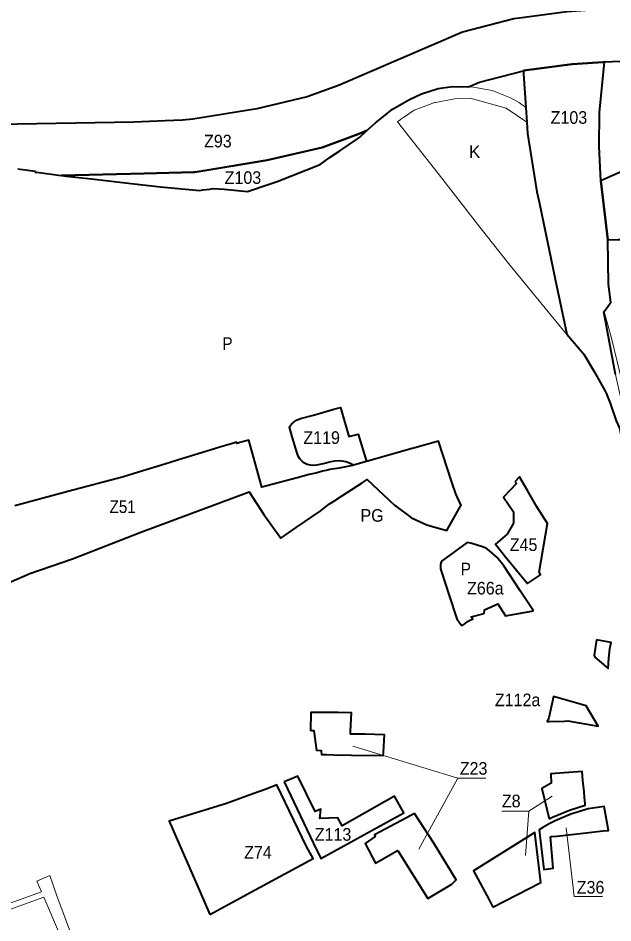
# Model space of a CAD drawing. Extents: x -650276 to -642489, y -1074311 to -1066658.
# Drawn here: x -649001 to -647871, y -1070690 to -1068970 of the extents above; entities that cross this region are included whole.
import ezdxf

# ---------------------------------------------------------------- set-up
doc = ezdxf.new("R2010")
doc.units = 0
doc.header["$LTSCALE"] = 9.6
for name, color, linetype, lineweight in [('44', 7, 'Continuous', 40), ('45', 7, 'Continuous', 40), ('46', 7, 'Continuous', 13), ('47', 7, 'Continuous', 13), ('48', 7, 'Continuous', 13), ('60', 7, 'Continuous', 35)]:
    doc.layers.add(name, color=color, linetype=linetype, lineweight=lineweight)

msp = doc.modelspace()

# ---------------------------------------------------------------- linework, layer by layer
at = {"layer": '44'}
for points in [[(-647749.978, -1068953.416), (-647850.043, -1068951.099), (-647864.531, -1068951.823), (-647895.901, -1068953.392), (-647958.168, -1068957.73), (-648038.596, -1068968.281), (-648038.596, -1068968.281), (-648038.746, -1068968.301), (-648058.764, -1068970.927)], [(-648058.764, -1068970.927), (-648156.739, -1068996.273), (-648392.002, -1069097.554), (-648451.865, -1069119.456), (-648547.243, -1069141.81), (-648668.959, -1069161.838), (-648688.912, -1069163.603), (-648721.315, -1069164.952), (-648781.015, -1069167.44), (-649076.02, -1069172.683)], [(-648040.456, -1069069.483), (-648039.666, -1069069.279), (-647948.18, -1069057.276)], [(-647948.18, -1069057.276), (-648039.666, -1069069.279), (-648040.456, -1069069.483)], [(-647948.18, -1069057.276), (-647889.927, -1069053.218), (-647886.615, -1069053.052)], [(-647886.615, -1069053.052), (-647889.927, -1069053.218), (-647948.18, -1069057.276)], [(-647887.087, -1069527.229), (-647878.73, -1069515.45), (-647874.75, -1069509.84), (-647878.93, -1069475.09), (-647880.326, -1069390.832), (-647893.553, -1069279.021), (-647896.67, -1069213.573), (-647896.362, -1069149.171), (-647886.615, -1069053.052)], [(-647886.615, -1069053.052), (-647856.541, -1069051.548), (-647756.441, -1069053.207), (-647708.401, -1069056.275), (-647511.94, -1069076.703), (-647426.417, -1069084.624), (-647344.902, -1069091.02), (-647270.522, -1069094.255), (-647197.498, -1069094.255), (-647123.648, -1069091.043), (-647065.688, -1069087.73)], [(-648665.007, -1069262.694), (-648527.693, -1069239.938), (-648423.173, -1069215.44), (-648354.978, -1069190.492), (-648338.523, -1069183.389), (-648322.14, -1069168.56), (-648306.83, -1069156.57), (-648289.25, -1069142.79), (-648257.5, -1069124.41), (-648234.22, -1069113.6), (-648202.46, -1069103.3), (-648175.65, -1069099.64), (-648144.866, -1069099.987), (-648124.327, -1069091.181), (-648040.705, -1069069.547), (-648040.456, -1069069.483)], [(-648040.456, -1069069.483), (-648040.537, -1069075.531), (-648036.291, -1069139.458), (-648034.421, -1069167.61)], [(-648526.15, -1069286.21), (-648508.95, -1069280.01), (-648427.08, -1069247.75), (-648407.73, -1069233.88), (-648389.91, -1069221.86), (-648355.81, -1069198.88), (-648351.77, -1069195.88), (-648338.523, -1069183.389), (-648354.978, -1069190.492)], [(-648034.421, -1069167.61), (-648033, -1069189), (-648015, -1069300), (-648010.092, -1069322.087), (-647980.331, -1069465.915), (-647958.34, -1069570.699), (-647925.99, -1069608.57)], [(-648354.978, -1069190.492), (-648423.173, -1069215.44), (-648527.693, -1069239.938), (-648652.716, -1069260.657)], [(-649001.3, -1069255.92), (-648968.49, -1069260.36), (-648968.05, -1069263.06), (-648965.8, -1069262.75), (-648937.91, -1069266.51), (-648924.13, -1069268.21), (-648918.889, -1069268.875)], [(-648918.889, -1069268.875), (-648761.189, -1069265.035), (-648666.827, -1069262.738), (-648665.007, -1069262.694)], [(-648666.827, -1069262.738), (-648761.189, -1069265.035), (-648918.889, -1069268.875), (-648909.86, -1069270.02), (-648861.49, -1069275.34), (-648785.92, -1069284.2), (-648730.66, -1069290.43), (-648730.66, -1069290.43), (-648655.53, -1069297.18), (-648650.06, -1069296.39), (-648636.85, -1069294.49)], [(-648652.716, -1069260.657), (-648665.007, -1069262.694), (-648666.827, -1069262.738)], [(-648636.85, -1069294.49), (-648630.82, -1069293.63), (-648609.425, -1069295.033), (-648603.228, -1069295.53), (-648565.18, -1069299.46), (-648526.15, -1069286.21)], [(-647865.69, -1069647.32), (-647887.649, -1069528.021), (-647887.087, -1069527.229)], [(-647925.99, -1069608.57), (-647906.16, -1069641.48), (-647885.665, -1069678.788), (-647885.663, -1069678.794), (-647883.51, -1069682.71), (-647875.82, -1069701.85)], [(-647875.82, -1069701.85), (-647864.19, -1069735.12), (-647858.44, -1069749.43), (-647852.63, -1069775.7), (-647850.66, -1069785.74), (-647849.165, -1069793.367), (-647843.74, -1069817.63), (-647841.402, -1069792.351)]]:
    msp.add_lwpolyline(points, dxfattribs=at)
msp.add_lwpolyline([(-647860.52, -1069390.72), (-647848.24, -1069390.65), (-647845.25, -1069390.07), (-647843.41, -1069389.23), (-647841.81, -1069387.99), (-647840.42, -1069386.51), (-647839.4, -1069384.73), (-647838.79, -1069382.86), (-647836.2, -1069362.68), (-647832.29, -1069338.58), (-647832.29, -1069338.58), (-647831.19, -1069320.69), (-647830.23, -1069305.38), (-647826.928, -1069253.199), (-647848.17, -1069259.21), (-647858.37, -1069263.03), (-647893.553, -1069279.017), (-647880.326, -1069390.832)], close=True, dxfattribs=at)
msp.add_arc((-648354.978, -1069190.492), 0.000000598, 264.13978, 298.69712, dxfattribs=at)
at = {"layer": '45'}
for points in [[(-648338.933, -1069812.492), (-648363.563, -1069819.352), (-648371.093, -1069815.602), (-648377.983, -1069813.332), (-648385.093, -1069811.952), (-648392.333, -1069811.482), (-648399.563, -1069811.922), (-648406.723, -1069813.272), (-648414.54, -1069815.288), (-648415.873, -1069815.632), (-648430.764, -1069818.704), (-648433.853, -1069819.342), (-648439.773, -1069820.012), (-648445.683, -1069819.552), (-648451.413, -1069818.022), (-648456.763, -1069815.432), (-648461.523, -1069811.902), (-648465.553, -1069807.532), (-648468.703, -1069802.482), (-648470.853, -1069796.942), (-648480.15, -1069765.358), (-648485.323, -1069747.432), (-648485.023, -1069746.592), (-648483.157, -1069743.818), (-648481.673, -1069741.612), (-648477.273, -1069737.482), (-648475.905, -1069736.566), (-648472.283, -1069734.142), (-648464.333, -1069730.932), (-648439.683, -1069724.232), (-648401.171, -1069713.196), (-648388.514, -1069709.779), (-648372.522, -1069765.283), (-648354.898, -1069760.328)], [(-648057.11, -1069851.12), (-648053.61, -1069854.64), (-648078.54, -1069880.01), (-648059.32, -1069908.27), (-648059.5, -1069929.52), (-648071.58, -1069950.39), (-648093.67, -1069969.42), (-648074.96, -1069993.46), (-648032.85, -1070044.73), (-648008.18, -1070028.25), (-648010.44, -1070023.66), (-648010.94, -1070022.65), (-647994.71, -1069930.53), (-648015.11, -1069898.98), (-648032.94, -1069867.46), (-648048.08, -1069841.95)], [(-648057.11, -1069851.12), (-648053.61, -1069854.64), (-648078.54, -1069880.01), (-648059.32, -1069908.27), (-648059.5, -1069929.52), (-648071.58, -1069950.39), (-648093.67, -1069969.42), (-648074.96, -1069993.46), (-648032.85, -1070044.73), (-648008.18, -1070028.25), (-648010.44, -1070023.66), (-648010.94, -1070022.65), (-647994.71, -1069930.53), (-648015.11, -1069898.98), (-648032.94, -1069867.46), (-648048.08, -1069841.95)], [(-647902.17, -1070151.64), (-647906.6, -1070180.65), (-647905.17, -1070184.5), (-647879.81, -1070206.08), (-647878.18, -1070186.33), (-647876.74, -1070168.88), (-647873.97, -1070156.58)], [(-647902.17, -1070151.64), (-647906.6, -1070180.65), (-647905.17, -1070184.5), (-647879.81, -1070206.08), (-647878.18, -1070186.33), (-647876.74, -1070168.88), (-647873.97, -1070156.58)], [(-647962.82, -1070305.9), (-647956.36, -1070305.77), (-647898.82, -1070315.51), (-647921.51, -1070276.76), (-647979.24, -1070260.71), (-647983.6, -1070259.5), (-647992.71, -1070300.01), (-647995.46, -1070306.55), (-647991.12, -1070306.46)], [(-648444.85, -1070324.47), (-648444.15, -1070289.16), (-648428.98, -1070288.92), (-648416.93, -1070288.85), (-648392.94, -1070289.25), (-648368.25, -1070289.71), (-648370.07, -1070325.94), (-648370.07, -1070329.902), (-648341.46, -1070330.48), (-648305.47, -1070331.23), (-648307.13, -1070365.57), (-648307.67, -1070371.78), (-648367.67, -1070371.16), (-648401.35, -1070370.5), (-648414.75, -1070370.24), (-648424.05, -1070370), (-648424.31, -1070362.21), (-648433.46, -1070361.94), (-648437.65, -1070328.8), (-648438.296, -1070324.598)], [(-648444.85, -1070324.47), (-648444.15, -1070289.16), (-648428.98, -1070288.92), (-648416.93, -1070288.85), (-648392.94, -1070289.25), (-648368.25, -1070289.71), (-648370.07, -1070325.94), (-648370.07, -1070329.902), (-648341.46, -1070330.48), (-648305.47, -1070331.23), (-648307.13, -1070365.57), (-648307.67, -1070371.78), (-648367.67, -1070371.16), (-648401.35, -1070370.5), (-648414.75, -1070370.24), (-648424.05, -1070370), (-648424.31, -1070362.21), (-648433.46, -1070361.94), (-648437.65, -1070328.8), (-648438.296, -1070324.598)], [(-647991.539, -1070492.016), (-647985.19, -1070488.804), (-647953.251, -1070475.276), (-647923.247, -1070465.749), (-647923.53, -1070462.75), (-647924.63, -1070451.09), (-647925.5, -1070439.63), (-647926.53, -1070429.76), (-647927.67, -1070418.74), (-647929.24, -1070401.97), (-647988.86, -1070405.95), (-647988.11, -1070423.93), (-648005.668, -1070434.145)], [(-648495.666, -1070421.476), (-648439.409, -1070538.729), (-648425.835, -1070567.021), (-648267.801, -1070480.55), (-648285.75, -1070448.49), (-648385.085, -1070505.351), (-648393.14, -1070490.07), (-648427.41, -1070491.08), (-648426.05, -1070473.34), (-648436.22, -1070478.01), (-648469.77, -1070410.47), (-648481.18, -1070415.62)], [(-648495.666, -1070421.476), (-648439.409, -1070538.729), (-648425.835, -1070567.021), (-648267.801, -1070480.55), (-648285.75, -1070448.49), (-648385.085, -1070505.351), (-648393.14, -1070490.07), (-648427.41, -1070491.08), (-648426.05, -1070473.34), (-648436.22, -1070478.01), (-648469.77, -1070410.47), (-648481.18, -1070415.62)], [(-648636.757, -1070673.431), (-648550.72, -1070626.869), (-648440.531, -1070567.236), (-648452.97, -1070544.21), (-648509.227, -1070426.957), (-648526.28, -1070433.85), (-648538.611, -1070438.388), (-648546.377, -1070441.246), (-648604.92, -1070462.79), (-648714.161, -1070496.376), (-648655.178, -1070631.294)], [(-647950.48, -1070482.79), (-647980.4, -1070495.463), (-647990.295, -1070500.352), (-648003.85, -1070508.218), (-648010.831, -1070512.588), (-648002, -1070588), (-647984.03, -1070585.46), (-647989.5, -1070525.73), (-647987.436, -1070525.508), (-647977.41, -1070524.43), (-647927.14, -1070519), (-647889.27, -1070514.92), (-647879.89, -1070513.91), (-647879.16, -1070513.83), (-647887.08, -1070468.54), (-647899.87, -1070470.04), (-647917.98, -1070472.47)], [(-648247.67, -1070481.57), (-648262.69, -1070489.67), (-648323.59, -1070522.48), (-648322.18, -1070525.44), (-648341.41, -1070538.42), (-648322.16, -1070575.76), (-648289.22, -1070557.15), (-648279.736, -1070551.783), (-648278.89, -1070553.14), (-648222.58, -1070643.48), (-648176.54, -1070616.09), (-648168.575, -1070607.847), (-648211, -1070538)], [(-648247.67, -1070481.57), (-648262.69, -1070489.67), (-648323.59, -1070522.48), (-648322.18, -1070525.44), (-648341.41, -1070538.42), (-648322.16, -1070575.76), (-648289.22, -1070557.15), (-648279.736, -1070551.783), (-648278.89, -1070553.14), (-648222.58, -1070643.48), (-648176.54, -1070616.09), (-648168.575, -1070607.847), (-648211, -1070538)], [(-648098.637, -1070659.682), (-648007.838, -1070612.851), (-648019, -1070518), (-648135.47, -1070590.61), (-648105.98, -1070645.91)]]:
    msp.add_lwpolyline(points, close=True, dxfattribs=at)
for points in [[(-649048.918, -1070055.852), (-648978.654, -1070025.669), (-648897.735, -1069997.25), (-648767.83, -1069946.87), (-648562.242, -1069870.301), (-648533.79, -1069913.49), (-648502.048, -1069957.969), (-648472.6, -1069937.81), (-648426.82, -1069906.88), (-648409.44, -1069893.25), (-648396.87, -1069885.43), (-648395.03, -1069884.22), (-648347.06, -1069853), (-648337.48, -1069846.531), (-648285.62, -1069895.71), (-648253.13, -1069919.7), (-648223.99, -1069932.96), (-648218.245, -1069934.595), (-648186.268, -1069943.697), (-648160.04, -1069897.73), (-648159.1, -1069896.39), (-648169.15, -1069873.81), (-648176.78, -1069851.74), (-648201.83, -1069773.86), (-648247.27, -1069786.64), (-648251.94, -1069787.95), (-648339.05, -1069812.45), (-648363.68, -1069819.31), (-648365.81, -1069819.9), (-648391.08, -1069825.45), (-648408.45, -1069827.83), (-648412.74, -1069828.72), (-648422.75, -1069830.78), (-648435.53, -1069834.44), (-648447.98, -1069837.44), (-648470.79, -1069843.51), (-648528.11, -1069858.73), (-648537.86, -1069861.22), (-648541.06, -1069849.78), (-648546.97, -1069828.68), (-648562.87, -1069771.85), (-648579.63, -1069776.66), (-648584.65, -1069778.1), (-648586.09, -1069775.75), (-648593.59, -1069778.06), (-648615.88, -1069784.93), (-648627.99, -1069788.67), (-648665.05, -1069799.99), (-648698.31, -1069810.16), (-648722.24, -1069817.54), (-648772.48, -1069832.83), (-648800.85, -1069841.52), (-648906.547, -1069869.711), (-649007.37, -1069896.602)], [(-648128.48, -1069971.7), (-648140.96, -1069968.01), (-648147.46, -1069966.19), (-648194.84, -1070000.49)], [(-648111.44, -1069977.32), (-648118.75, -1069974.53), (-648128.48, -1069971.7)], [(-648021.35, -1070096.14), (-648046.83, -1070058.62), (-648077.68, -1070011.06), (-648091.06, -1069994.07), (-648105.79, -1069981.56), (-648111.44, -1069977.32)], [(-648194.84, -1070000.49), (-648197.19, -1070003.94), (-648198.17, -1070008.05), (-648198.48, -1070012.3), (-648198.22, -1070016.4), (-648197.23, -1070020.37), (-648182.01, -1070067.11)], [(-648182.01, -1070067.11), (-648167.48, -1070111.75), (-648159.89, -1070122.49), (-648159.02, -1070123.71), (-648156.07, -1070123.54)], [(-648115.11, -1070101.26), (-648114.7, -1070094.68), (-648089.22, -1070083.27), (-648074.76, -1070106.17), (-648021.35, -1070096.14)], [(-648152.35, -1070121.05), (-648147.02, -1070116.35), (-648139.45, -1070112.79), (-648136.61, -1070111.97), (-648139.91, -1070107.48), (-648115.11, -1070101.26)], [(-648156.07, -1070123.54), (-648153.85, -1070122.38), (-648152.35, -1070121.05)]]:
    msp.add_lwpolyline(points, dxfattribs=at)
at = {"layer": '46'}
for p, q in [((-648165.109, -1070414.543), (-648239.52, -1070549.62)), ((-648165.109, -1070414.543), (-648239.52, -1070549.62)), ((-648030.462, -1070477.049), (-648036.992, -1070561.483)), ((-647944.293, -1070639.492), (-647959.279, -1070509.201)), ((-647890.215, -1070639.492), (-647944.293, -1070639.492)), ((-647890.215, -1070639.492), (-647904.43, -1070639.492))]:
    msp.add_line(p, q, dxfattribs=at)
for points in [[(-648112.329, -1070414.543), (-648165.109, -1070414.543), (-648364.98, -1070353.932)], [(-648112.329, -1070414.543), (-648165.109, -1070414.543), (-648364.98, -1070353.932)], [(-648081.63, -1070477.049), (-648030.462, -1070477.049), (-647985.902, -1070448.995)]]:
    msp.add_lwpolyline(points, dxfattribs=at)
at = {"layer": '47'}
for points in [[(-648036.291, -1069139.458), (-648040.537, -1069075.531), (-648040.5, -1069072.79), (-648040.705, -1069069.548), (-648124.327, -1069091.181), (-648144.866, -1069099.987)], [(-648144.866, -1069099.987), (-648139.27, -1069100.05), (-648100.37, -1069107.1), (-648100.37, -1069107.1), (-648065.16, -1069121.12)], [(-648065.16, -1069121.12), (-648048.06, -1069130.81), (-648036.291, -1069139.458)]]:
    msp.add_lwpolyline(points, dxfattribs=at)
for points in [[(-648127.77, -1069361.38), (-648068.71, -1069436.57), (-647967.53, -1069559.94), (-647958.214, -1069571.3), (-647980.331, -1069465.915), (-648010.092, -1069322.087), (-648015, -1069300), (-648033, -1069189), (-648034.421, -1069167.61), (-648073.66, -1069140.86), (-648141.92, -1069121.66), (-648171.14, -1069122.83), (-648207.77, -1069129.95), (-648209.89, -1069130.36), (-648226.51, -1069136.57), (-648248.14, -1069144.65), (-648268.87, -1069158.61), (-648270.92, -1069159.99), (-648275.19, -1069162.87), (-648280.1, -1069166.97), (-648203.01, -1069264.73)], [(-647845.086, -1069748.753), (-647842.438, -1069760.647), (-647844.371, -1069761.991), (-647843.337, -1069769.013), (-647822.54, -1069759.29), (-647830, -1069744.7), (-647835.76, -1069730.01), (-647845.85, -1069691.2), (-647852.44, -1069664.03), (-647873.43, -1069577.87), (-647887.087, -1069527.229), (-647865.69, -1069647.32), (-647855.158, -1069695.232), (-647846.484, -1069736.663)], [(-649014.888, -1070782.994), (-648966.35, -1070764.7), (-648908.94, -1070740.19), (-648892.215, -1070733.293), (-648927.2, -1070637.98), (-648941.064, -1070599.735), (-648965.569, -1070610.382), (-648956.687, -1070630.825), (-649050.081, -1070663.981), (-649047.11, -1070674.743), (-648952.455, -1070640.564), (-648922.196, -1070710.207), (-648924.668, -1070712.022), (-648943.837, -1070720.104), (-649025.129, -1070754.377)]]:
    msp.add_lwpolyline(points, close=True, dxfattribs=at)

# ---------------------------------------------------------------- texts
at = {"layer": '44', "width": 0.95}
for s, p in [('Z103', (-647989.032, -1069170.515)), ('Z103', (-647989.032, -1069170.515)), ('Z93', (-648647.673, -1069215.426)), ('Z93', (-648647.673, -1069215.426)), ('Z103', (-648608.542, -1069284.81)), ('Z103', (-648608.542, -1069284.81))]:
    msp.add_text(s, height=24, dxfattribs=at).set_placement(p)
at = {"layer": '46'}
for s, width, p in [('Z119', 0.95, (-648458.914, -1069779.092)), ('Z51', 0.9, (-648827.214, -1069910.388)), ('Z45', 0.95, (-648066.663, -1069982.614)), ('Z45', 0.95, (-648066.663, -1069982.614)), ('Z66a', 0.95, (-648147.889, -1070065.308)), ('Z112a', 0.95, (-648094.972, -1070277.658)), ('Z23', 0.95, (-648161.708, -1070407.912)), ('Z23', 0.95, (-648161.708, -1070407.912)), ('Z8', 0.95, (-648081.661, -1070469.822)), ('Z113', 0.95, (-648437.324, -1070533.384)), ('Z113', 0.95, (-648437.324, -1070533.384)), ('Z74', 0.95, (-648571.565, -1070567.472)), ('Z36', 0.95, (-647939.415, -1070633.92)), ('Z36', 0.95, (-647939.415, -1070633.92))]:
    msp.add_text(s, height=24, dxfattribs=dict(at, width=width)).set_placement(p)
at = {"layer": '48'}
msp.add_text('K', height=24, dxfattribs=at).set_placement((-648144.004, -1069235.577))
msp.add_text('K', height=24, dxfattribs=at).set_placement((-648144.004, -1069235.577))
at = {"layer": '60'}
for s, width, p in [('P', 0.9, (-648612.658, -1069600.244)), ('PG', 0.95, (-648350.408, -1069926.995)), ('P', 0.9, (-648159.699, -1070028.97))]:
    msp.add_text(s, height=24, dxfattribs=dict(at, width=width)).set_placement(p)

doc.saveas('drawing.dxf')
